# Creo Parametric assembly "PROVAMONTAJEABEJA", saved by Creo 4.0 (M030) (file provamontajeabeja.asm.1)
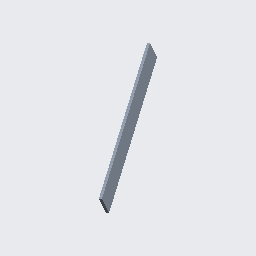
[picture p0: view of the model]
Units: millimeter Newton Second (mmNs); MM, TONNE, SECS

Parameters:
  MODELED_BY = "aj"

Created from: MMNS_ASM_DESIGN.ASM

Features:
  1. datum plane "ASM_RIGHT"
  2. datum plane "ASM_TOP"
  3. datum plane "ASM_FRONT"
  4. coordinate system
  5. component "RAMPA"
